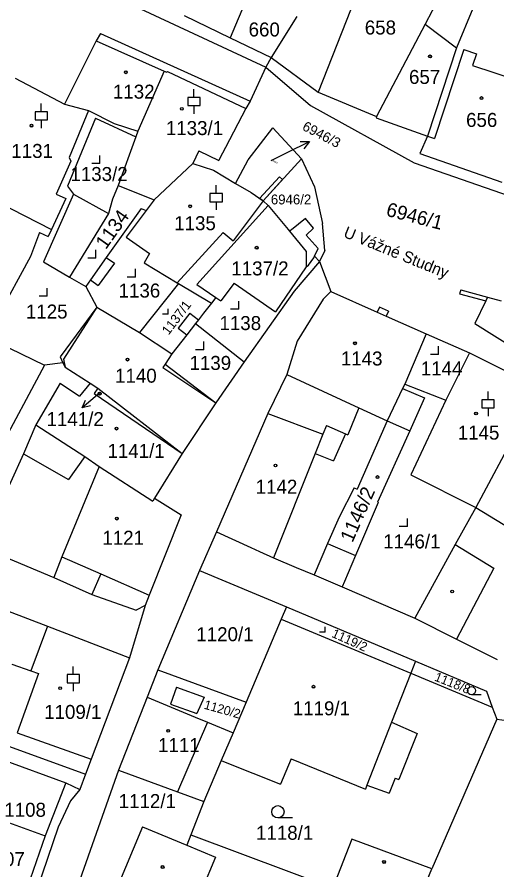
# Model space of a CAD drawing. Extents: x -593183 to -588034, y -1130415 to -1124994.
# Drawn here: x -591094.9 to -591036.6, y -1128971.4 to -1128867.8 of the extents above; entities that cross this region are included whole.
import ezdxf

# ---------------------------------------------------------------- set-up
doc = ezdxf.new("R2010")
doc.units = 0
for name, color, linetype in [('Vrstva 1', 7, 'Continuous'), ('Vrstva 15', 7, 'Continuous'), ('Vrstva 16', 7, 'Continuous'), ('Vrstva 18', 7, 'Continuous'), ('Vrstva 19', 7, 'Continuous'), ('Vrstva 25', 7, 'Continuous'), ('Vrstva 27', 7, 'Continuous'), ('Vrstva 4', 7, 'Continuous')]:
    doc.layers.add(name, color=color, linetype=linetype)

msp = doc.modelspace()

# ---------------------------------------------------------------- linework, layer by layer
at = {"layer": 'Vrstva 1'}
for p, q in [((-591051.99, -1128860.88), (-591058.32, -1128876.96)), ((-591042.27, -1128862.83), (-591045.35, -1128868.7)), ((-591066.71, -1128864.82), (-591069.01, -1128870.37)), ((-591074.6, -1128867.65), (-591069.01, -1128870.37)), ((-591060.94, -1128867.77), (-591064.03, -1128872.76)), ((-591039.55, -1128866.8), (-591041.52, -1128871.56)), ((-591045.35, -1128868.7), (-591051.24, -1128879.91)), ((-591085.29, -1128870.72), (-591089.14, -1128878.39)), ((-591085.29, -1128870.72), (-591077.03, -1128874.4)), ((-591069.01, -1128870.37), (-591064.03, -1128872.76)), ((-591041.52, -1128871.56), (-591045.06, -1128882.28)), ((-591064.03, -1128872.76), (-591064.7, -1128873.91)), ((-591064.03, -1128872.76), (-591058.32, -1128876.96)), ((-591064.7, -1128873.91), (-591066.58, -1128878.04)), ((-591077.03, -1128874.4), (-591080.25, -1128881.7)), ((-591077.03, -1128874.4), (-591076.7, -1128874.53)), ((-591076.64, -1128874.43), (-591076.7, -1128874.53)), ((-591076.64, -1128874.43), (-591067.1, -1128878.93)), ((-591095.14, -1128875.24), (-591089.14, -1128878.39)), ((-591058.32, -1128876.96), (-591051.24, -1128879.91)), ((-591066.58, -1128878.04), (-591067.1, -1128878.93)), ((-591089.14, -1128878.39), (-591086.22, -1128879.16)), ((-591086.22, -1128879.16), (-591088.58, -1128884.9)), ((-591086.22, -1128879.16), (-591083.09, -1128880.74)), ((-591067.1, -1128878.93), (-591069.59, -1128883.68)), ((-591085.38, -1128880.09), (-591088.79, -1128888.37)), ((-591085.38, -1128880.09), (-591080.47, -1128882.37)), ((-591051.24, -1128879.91), (-591051.28, -1128880.06)), ((-591051.28, -1128880.06), (-591045.06, -1128882.28)), ((-591083.09, -1128880.74), (-591080.25, -1128881.7)), ((-591080.25, -1128881.7), (-591080.47, -1128882.37)), ((-591066.83, -1128885.16), (-591063.83, -1128881.29)), ((-591063.83, -1128881.29), (-591060.37, -1128885.05)), ((-591045.06, -1128882.28), (-591045.98, -1128884.39)), ((-591080.47, -1128882.37), (-591082.61, -1128888.27)), ((-591072.81, -1128884.07), (-591073.57, -1128885.62)), ((-591072.81, -1128884.07), (-591070.41, -1128885.25)), ((-591069.59, -1128883.68), (-591070.3, -1128885.04)), ((-591045.98, -1128884.39), (-591036.02, -1128887.89)), ((-591088.36, -1128885.32), (-591090.17, -1128889.33)), ((-591088.58, -1128884.9), (-591088.36, -1128885.32)), ((-591070.3, -1128885.04), (-591070.41, -1128885.25)), ((-591068.37, -1128888.03), (-591066.83, -1128885.16)), ((-591065.02, -1128890.15), (-591060.37, -1128885.05)), ((-591060.37, -1128885.05), (-591058.79, -1128888.43)), ((-591073.57, -1128885.62), (-591078.24, -1128890.04)), ((-591073.57, -1128885.62), (-591071.04, -1128886.44)), ((-591071.04, -1128886.44), (-591068.37, -1128888.03)), ((-591101.51, -1128888.11), (-591090.72, -1128893.62)), ((-591088.79, -1128888.37), (-591088.04, -1128889.34)), ((-591082.61, -1128888.27), (-591083.32, -1128889.93)), ((-591082.61, -1128888.27), (-591078.24, -1128890.04)), ((-591068.37, -1128888.03), (-591066.47, -1128889.15)), ((-591058.79, -1128888.43), (-591057.81, -1128892.89)), ((-591088.04, -1128889.34), (-591091.69, -1128897.56)), ((-591090.17, -1128889.33), (-591088.99, -1128889.86)), ((-591066.47, -1128889.15), (-591065.02, -1128890.15)), ((-591088.99, -1128889.86), (-591090.72, -1128893.62)), ((-591083.32, -1128889.93), (-591083.78, -1128891.69)), ((-591078.24, -1128890.04), (-591079.23, -1128891.33)), ((-591065.02, -1128890.15), (-591068.66, -1128895)), ((-591065.02, -1128890.15), (-591064.39, -1128890.73)), ((-591079.83, -1128891.06), (-591084.06, -1128897.03)), ((-591079.23, -1128891.33), (-591081.65, -1128894.54)), ((-591079.83, -1128891.06), (-591079.23, -1128891.33)), ((-591064.39, -1128890.73), (-591073.07, -1128900.31)), ((-591064.39, -1128890.73), (-591061.98, -1128893.63)), ((-591083.78, -1128891.69), (-591088.52, -1128899.43)), ((-591059.87, -1128892.31), (-591061.58, -1128893.66)), ((-591058.9, -1128893.46), (-591059.87, -1128892.31)), ((-591090.72, -1128893.62), (-591091.11, -1128894.46)), ((-591061.98, -1128893.63), (-591061.81, -1128893.84)), ((-591061.58, -1128893.66), (-591061.81, -1128893.84)), ((-591059.77, -1128894.32), (-591058.9, -1128893.46)), ((-591057.51, -1128896.18), (-591057.81, -1128892.89)), ((-591092.18, -1128894.01), (-591093.28, -1128896.89)), ((-591092.18, -1128894.01), (-591091.11, -1128894.46)), ((-591081.65, -1128894.54), (-591078.8, -1128896.53)), ((-591069.86, -1128894.01), (-591075.45, -1128900.09)), ((-591069.86, -1128894.01), (-591068.66, -1128895)), ((-591058.33, -1128895.94), (-591059.77, -1128894.32)), ((-591078.8, -1128896.53), (-591079.48, -1128897.67)), ((-591058.76, -1128896.86), (-591058.33, -1128895.94)), ((-591057.51, -1128896.18), (-591058.18, -1128897.51)), ((-591093.28, -1128896.89), (-591098.41, -1128906.34)), ((-591091.69, -1128897.56), (-591088.52, -1128899.43)), ((-591084.06, -1128897.03), (-591085.98, -1128899.74)), ((-591079.48, -1128897.67), (-591075.45, -1128900.09)), ((-591058.18, -1128897.51), (-591061.26, -1128901.13)), ((-591059.52, -1128897.96), (-591058.86, -1128897.07)), ((-591058.86, -1128897.07), (-591058.76, -1128896.86)), ((-591058.18, -1128897.51), (-591058.76, -1128896.86)), ((-591058.18, -1128897.51), (-591056.81, -1128901.17)), ((-591059.77, -1128898.17), (-591063.53, -1128903.61)), ((-591059.77, -1128898.17), (-591059.52, -1128897.96)), ((-591088.52, -1128899.43), (-591086.56, -1128900.56)), ((-591085.98, -1128899.74), (-591086.56, -1128900.56)), ((-591086.56, -1128900.56), (-591085.23, -1128903.06)), ((-591075.28, -1128900.19), (-591080.02, -1128906.15)), ((-591075.45, -1128900.09), (-591075.28, -1128900.19)), ((-591073.07, -1128900.31), (-591070.75, -1128901.88)), ((-591068.52, -1128900.15), (-591070.14, -1128902.3)), ((-591068.52, -1128900.15), (-591063.53, -1128903.61)), ((-591070.75, -1128901.88), (-591071.3, -1128902.58)), ((-591070.75, -1128901.88), (-591070.14, -1128902.3)), ((-591061.26, -1128901.13), (-591067.34, -1128909.69)), ((-591056.81, -1128901.17), (-591057.74, -1128902.09)), ((-591056.81, -1128901.17), (-591051.17, -1128903.66)), ((-591037.77, -1128901.83), (-591037.98, -1128902.28)), ((-591037.77, -1128901.83), (-591036.1, -1128902.27)), ((-591071.3, -1128902.58), (-591072.25, -1128903.79)), ((-591057.74, -1128902.09), (-591060.9, -1128907.17)), ((-591037.98, -1128902.28), (-591039.3, -1128905.06)), ((-591085.23, -1128903.06), (-591089.65, -1128909.1)), ((-591085.23, -1128903.06), (-591080.02, -1128906.15)), ((-591072.25, -1128903.79), (-591072.88, -1128904.6)), ((-591051.17, -1128903.66), (-591050.07, -1128904.14)), ((-591073.24, -1128905.06), (-591074.29, -1128906.4)), ((-591072.88, -1128904.6), (-591073.24, -1128905.06)), ((-591073.24, -1128905.06), (-591067.34, -1128909.69)), ((-591050.07, -1128904.14), (-591045.2, -1128906.29)), ((-591039.3, -1128905.06), (-591031.08, -1128910.21)), ((-591098.31, -1128906.84), (-591091.56, -1128910.11)), ((-591080.02, -1128906.15), (-591076.1, -1128908.71)), ((-591074.29, -1128906.4), (-591076.1, -1128908.71)), ((-591060.9, -1128907.17), (-591062.14, -1128911.23)), ((-591045.2, -1128906.29), (-591047.79, -1128912.4)), ((-591045.2, -1128906.29), (-591039.97, -1128908.62)), ((-591089.65, -1128909.1), (-591089.36, -1128909.81)), ((-591076.1, -1128908.71), (-591076.93, -1128909.96)), ((-591039.97, -1128908.62), (-591042.81, -1128914.37)), ((-591039.97, -1128908.62), (-591031.44, -1128912.87)), ((-591091.56, -1128910.11), (-591098.56, -1128923.14)), ((-591089.36, -1128909.81), (-591091.56, -1128910.11)), ((-591089.36, -1128909.81), (-591089.06, -1128910.34)), ((-591076.93, -1128909.96), (-591070.76, -1128914.69)), ((-591067.34, -1128909.69), (-591070.76, -1128914.69)), ((-591089.06, -1128910.34), (-591086.04, -1128912.29)), ((-591062.14, -1128911.23), (-591064.46, -1128915.98)), ((-591089.66, -1128912.27), (-591092.62, -1128917.34)), ((-591089.66, -1128912.27), (-591087.31, -1128913.85)), ((-591086.04, -1128912.29), (-591087.31, -1128913.85)), ((-591086.04, -1128912.29), (-591085.1, -1128912.88)), ((-591085.1, -1128912.88), (-591085.53, -1128913.55)), ((-591085.1, -1128912.88), (-591074.83, -1128920.84)), ((-591048.08, -1128912.94), (-591049.94, -1128916.85)), ((-591047.79, -1128912.4), (-591048.08, -1128912.94)), ((-591047.79, -1128912.4), (-591042.81, -1128914.37)), ((-591031.44, -1128912.87), (-591039.19, -1128927.37)), ((-591085.53, -1128913.55), (-591074.83, -1128920.84)), ((-591042.81, -1128914.37), (-591047.09, -1128923.42)), ((-591070.76, -1128914.69), (-591074.83, -1128920.84)), ((-591064.46, -1128915.98), (-591070.68, -1128930.35)), ((-591064.46, -1128915.98), (-591057.76, -1128918.48)), ((-591092.62, -1128917.34), (-591094.1, -1128920.87)), ((-591049.94, -1128916.85), (-591053.58, -1128925.15)), ((-591049.94, -1128916.85), (-591047.21, -1128918.09)), ((-591057.76, -1128918.48), (-591058.7, -1128920.84)), ((-591047.21, -1128918.09), (-591051.12, -1128926.74)), ((-591094.1, -1128920.87), (-591099.1, -1128931.74)), ((-591094.1, -1128920.87), (-591088.66, -1128923.98)), ((-591086.68, -1128921.19), (-591088.66, -1128923.98)), ((-591086.68, -1128921.19), (-591084.94, -1128922.4)), ((-591074.83, -1128920.84), (-591078.2, -1128926.25)), ((-591058.7, -1128920.84), (-591063.76, -1128933.51)), ((-591084.94, -1128922.4), (-591078.43, -1128926.63)), ((-591047.09, -1128923.42), (-591039.19, -1128927.37)), ((-591053.97, -1128924.99), (-591055.8, -1128928.57)), ((-591053.97, -1128924.99), (-591053.58, -1128925.15)), ((-591078.2, -1128926.25), (-591078.43, -1128926.63)), ((-591078.2, -1128926.25), (-591074.99, -1128928.29)), ((-591051.03, -1128926.78), (-591053.79, -1128933.21)), ((-591051.12, -1128926.74), (-591051.03, -1128926.78)), ((-591039.19, -1128927.37), (-591041.71, -1128931.87)), ((-591074.99, -1128928.29), (-591078.85, -1128938.01)), ((-591055.8, -1128928.57), (-591057.18, -1128931.76)), ((-591070.68, -1128930.35), (-591072.75, -1128935.02)), ((-591070.68, -1128930.35), (-591066.5, -1128932.26)), ((-591057.18, -1128931.76), (-591058.81, -1128935.54)), ((-591057.18, -1128931.76), (-591056.82, -1128931.91)), ((-591056.82, -1128931.91), (-591053.79, -1128933.21)), ((-591041.71, -1128931.87), (-591046.61, -1128940.82)), ((-591098.01, -1128932.7), (-591090.43, -1128935.9)), ((-591066.5, -1128932.26), (-591065.47, -1128932.73)), ((-591065.47, -1128932.73), (-591063.76, -1128933.51)), ((-591063.76, -1128933.51), (-591061.02, -1128934.66)), ((-591072.75, -1128935.02), (-591077.82, -1128947.1)), ((-591072.75, -1128935.02), (-591062.19, -1128939.46)), ((-591061.02, -1128934.66), (-591058.81, -1128935.54)), ((-591090.43, -1128935.9), (-591085.84, -1128937.95)), ((-591058.81, -1128935.54), (-591055.42, -1128937.01)), ((-591055.42, -1128937.01), (-591046.61, -1128940.82)), ((-591085.84, -1128937.95), (-591080.43, -1128939.84)), ((-591078.85, -1128938.01), (-591079.35, -1128939.28)), ((-591079.35, -1128939.28), (-591081.24, -1128945.62)), ((-591079.35, -1128939.28), (-591080.43, -1128939.84)), ((-591096.05, -1128939.94), (-591091.21, -1128941.8)), ((-591062.19, -1128939.46), (-591062.82, -1128940.94)), ((-591062.19, -1128939.46), (-591046.51, -1128946.03)), ((-591062.82, -1128940.94), (-591067.09, -1128951.04)), ((-591062.82, -1128940.94), (-591047.08, -1128947.49)), ((-591046.61, -1128940.82), (-591041.54, -1128943.37)), ((-591091.21, -1128941.8), (-591081.24, -1128945.62)), ((-591041.54, -1128943.37), (-591036.59, -1128945.84)), ((-591081.24, -1128945.62), (-591085.9, -1128957.94)), ((-591046.51, -1128946.03), (-591047.08, -1128947.49)), ((-591046.51, -1128946.03), (-591037.89, -1128949.67)), ((-591077.82, -1128947.1), (-591079.12, -1128950.43)), ((-591077.82, -1128947.1), (-591067.09, -1128951.04)), ((-591047.08, -1128947.49), (-591049.41, -1128953.45)), ((-591047.08, -1128947.49), (-591037.19, -1128951.61)), ((-591079.12, -1128950.43), (-591082.57, -1128959.29)), ((-591079.12, -1128950.43), (-591076.69, -1128951.44)), ((-591037.89, -1128949.67), (-591037.19, -1128951.61)), ((-591076.69, -1128951.44), (-591073.29, -1128952.84)), ((-591067.09, -1128951.04), (-591068.66, -1128954.76)), ((-591037.19, -1128951.61), (-591036.65, -1128953.09)), ((-591073.29, -1128952.84), (-591071.79, -1128953.46)), ((-591071.79, -1128953.46), (-591068.66, -1128954.76)), ((-591049.41, -1128953.45), (-591046.31, -1128954.81)), ((-591036.65, -1128953.09), (-591044.51, -1128971.27)), ((-591036.65, -1128953.09), (-591021.77, -1128955.01)), ((-591068.66, -1128954.76), (-591070.1, -1128958.12)), ((-591046.31, -1128954.81), (-591048.53, -1128960.43)), ((-591096.71, -1128956.08), (-591086.59, -1128959.76)), ((-591061.6, -1128957.91), (-591062.91, -1128960.96)), ((-591061.6, -1128957.91), (-591052.59, -1128961.59)), ((-591096.73, -1128958), (-591088.99, -1128960.83)), ((-591085.9, -1128957.94), (-591086.59, -1128959.76)), ((-591070.1, -1128958.12), (-591072.2, -1128963.09)), ((-591070.1, -1128958.12), (-591069.63, -1128958.31)), ((-591069.63, -1128958.31), (-591062.91, -1128960.96)), ((-591082.57, -1128959.29), (-591087.52, -1128973.28)), ((-591086.59, -1128959.76), (-591087.29, -1128961.61)), ((-591082.57, -1128959.29), (-591075.43, -1128961.91)), ((-591088.99, -1128960.83), (-591091.5, -1128967.24)), ((-591088.99, -1128960.83), (-591087.29, -1128961.61)), ((-591048.99, -1128960.25), (-591049.71, -1128962.06)), ((-591048.99, -1128960.25), (-591048.53, -1128960.43)), ((-591075.43, -1128961.91), (-591072.2, -1128963.09)), ((-591052.41, -1128961.12), (-591052.59, -1128961.59)), ((-591052.41, -1128961.12), (-591049.71, -1128962.06)), ((-591072.2, -1128963.09), (-591073.78, -1128967.13)), ((-591099.09, -1128964.52), (-591091.5, -1128967.24)), ((-591079.68, -1128966.15), (-591083.27, -1128974.76)), ((-591079.68, -1128966.15), (-591074.29, -1128968.39)), ((-591091.5, -1128967.24), (-591093.68, -1128973.55)), ((-591073.78, -1128967.13), (-591074.29, -1128968.39)), ((-591073.78, -1128967.13), (-591047.03, -1128977.11)), ((-591054.24, -1128967.67), (-591056.33, -1128973.04)), ((-591044.51, -1128971.27), (-591054.24, -1128967.67)), ((-591074.29, -1128968.39), (-591070.81, -1128969.83)), ((-591070.81, -1128969.83), (-591074.46, -1128978.6)), ((-591046.85, -1128976.69), (-591044.51, -1128971.27))]:
    msp.add_line(p, q, dxfattribs=at)
at = {"layer": 'Vrstva 16'}
msp.add_line((-591064.06, -1128885.25), (-591062.08, -1128884.28), dxfattribs=at)
at = {"layer": 'Vrstva 25'}
for p, q in [((-591073.43, -1128877.58), (-591073.43, -1128876.58)), ((-591091.97, -1128879.32), (-591091.97, -1128878.32)), ((-591073.43, -1128878.58), (-591073.43, -1128879.58)), ((-591091.97, -1128880.32), (-591091.97, -1128881.32)), ((-591062.08, -1128884.28), (-591059.38, -1128882.96)), ((-591084.83, -1128885.63), (-591084.83, -1128884.63)), ((-591084.83, -1128885.63), (-591085.83, -1128885.63)), ((-591070.72, -1128889.25), (-591070.72, -1128888.25)), ((-591070.72, -1128890.25), (-591070.72, -1128891.25)), ((-591085.32, -1128897.09), (-591085.32, -1128896.09)), ((-591085.32, -1128897.09), (-591086.32, -1128897.09)), ((-591080.52, -1128899.4), (-591080.52, -1128898.4)), ((-591080.52, -1128899.4), (-591081.52, -1128899.4)), ((-591091.23, -1128901.74), (-591091.23, -1128900.74)), ((-591091.23, -1128901.74), (-591092.23, -1128901.74)), ((-591067.97, -1128903.31), (-591067.97, -1128902.31)), ((-591076.55, -1128903.91), (-591077.22, -1128903.91)), ((-591076.55, -1128903.91), (-591076.55, -1128903.24)), ((-591067.97, -1128903.31), (-591068.97, -1128903.31)), ((-591072.23, -1128908.23), (-591072.23, -1128907.23)), ((-591043.7, -1128908.81), (-591043.7, -1128907.81)), ((-591072.23, -1128908.23), (-591073.23, -1128908.23)), ((-591043.7, -1128908.81), (-591044.7, -1128908.81)), ((-591037.69, -1128914.29), (-591037.69, -1128913.29)), ((-591084.9, -1128913.49), (-591086.98, -1128915.3)), ((-591037.69, -1128915.29), (-591037.69, -1128916.29)), ((-591047.49, -1128929.7), (-591047.49, -1128928.7)), ((-591047.49, -1128929.7), (-591048.49, -1128929.7)), ((-591057.49, -1128942.53), (-591057.49, -1128941.86)), ((-591057.49, -1128942.53), (-591058.16, -1128942.53)), ((-591088.07, -1128947.68), (-591088.07, -1128946.68)), ((-591088.07, -1128948.68), (-591088.07, -1128949.68)), ((-591038.54, -1128950.12), (-591039.71, -1128950.12)), ((-591061.47, -1128965.08), (-591063.22, -1128965.08))]:
    msp.add_line(p, q, dxfattribs=at)
for points in [[(-591074.18, -1128878.58), (-591072.68, -1128878.58), (-591072.68, -1128877.58), (-591074.18, -1128877.58)], [(-591092.72, -1128880.32), (-591091.22, -1128880.32), (-591091.22, -1128879.32), (-591092.72, -1128879.32)], [(-591071.47, -1128890.25), (-591069.97, -1128890.25), (-591069.97, -1128889.25), (-591071.47, -1128889.25)], [(-591038.44, -1128915.29), (-591036.94, -1128915.29), (-591036.94, -1128914.29), (-591038.44, -1128914.29)], [(-591088.82, -1128948.68), (-591087.32, -1128948.68), (-591087.32, -1128947.68), (-591088.82, -1128947.68)]]:
    msp.add_lwpolyline(points, close=True, dxfattribs=at)
for points in [[(-591060.5, -1128882.95), (-591059.38, -1128882.96), (-591060.06, -1128883.85)], [(-591085.99, -1128915.04), (-591086.98, -1128915.3), (-591086.59, -1128914.35)]]:
    msp.add_lwpolyline(points, dxfattribs=at)
for centre, radius in [((-591044.75, -1128872.61), 0.175), ((-591044.75, -1128872.61), 0.15), ((-591081.69, -1128874.53), 0.175), ((-591081.69, -1128874.53), 0.15), ((-591038.5, -1128877.67), 0.175), ((-591038.5, -1128877.67), 0.15), ((-591074.89, -1128878.97), 0.175), ((-591074.89, -1128878.97), 0.15), ((-591093.15, -1128881.02), 0.175), ((-591093.15, -1128881.02), 0.15), ((-591073.88, -1128890.81), 0.175), ((-591073.88, -1128890.81), 0.15), ((-591065.8, -1128895.84), 0.175), ((-591065.8, -1128895.84), 0.15), ((-591053.87, -1128907.44), 0.175), ((-591053.87, -1128907.44), 0.15), ((-591081.49, -1128909.42), 0.175), ((-591081.49, -1128909.42), 0.15), ((-591084.87, -1128913.56), 0.175), ((-591084.87, -1128913.56), 0.15), ((-591039.16, -1128915.97), 0.175), ((-591039.16, -1128915.97), 0.15), ((-591082.82, -1128917.8), 0.175), ((-591082.82, -1128917.8), 0.15), ((-591063.52, -1128922.28), 0.175), ((-591063.52, -1128922.28), 0.15), ((-591051.13, -1128923.69), 0.175), ((-591051.13, -1128923.69), 0.15), ((-591082.79, -1128928.73), 0.175), ((-591082.79, -1128928.73), 0.15), ((-591042.06, -1128937.58), 0.175), ((-591089.67, -1128949.32), 0.175), ((-591089.67, -1128949.32), 0.15), ((-591058.9, -1128949.15), 0.175), ((-591058.9, -1128949.15), 0.15), ((-591039.71, -1128949.62), 0.503), ((-591076.55, -1128954.51), 0.175), ((-591076.55, -1128954.51), 0.15), ((-591063.22, -1128964.33), 0.75), ((-591050.33, -1128970.43), 0.175), ((-591050.33, -1128970.43), 0.15), ((-591077.23, -1128971.04), 0.175), ((-591077.23, -1128971.04), 0.15)]:
    msp.add_circle(centre, radius, dxfattribs=at)
at = {"layer": 'Vrstva 27'}
for p, q in [((-591065.44, -1128889.86), (-591063.03, -1128887.22)), ((-591063.03, -1128887.22), (-591062.66, -1128887.56)), ((-591062.66, -1128887.56), (-591065.02, -1128890.15)), ((-591065.02, -1128890.15), (-591065.44, -1128889.86))]:
    msp.add_line(p, q, dxfattribs=at)
at = {"layer": 'Vrstva 4'}
for p, q in [((-591084.06, -1128864.87), (-591064.7, -1128873.91)), ((-591045.35, -1128868.7), (-591041.52, -1128871.56)), ((-591084.75, -1128869.81), (-591085.29, -1128870.72)), ((-591084.75, -1128869.81), (-591066.58, -1128878.04)), ((-591040.63, -1128871.78), (-591044.21, -1128882.59)), ((-591040.63, -1128871.78), (-591039.1, -1128872.28)), ((-591039.1, -1128872.28), (-591039.57, -1128873.71)), ((-591064.7, -1128873.91), (-591059.28, -1128878.58)), ((-591039.57, -1128873.71), (-591034.39, -1128875.42)), ((-591059.28, -1128878.58), (-591046.66, -1128885.54)), ((-591045.06, -1128882.28), (-591044.21, -1128882.59)), ((-591046.66, -1128885.54), (-591027, -1128892.39)), ((-591088.04, -1128889.34), (-591083.78, -1128891.69)), ((-591061.81, -1128893.84), (-591059.78, -1128896.28)), ((-591059.78, -1128896.28), (-591059.77, -1128898.17)), ((-591083.06, -1128897.73), (-591085.04, -1128900.41)), ((-591084.06, -1128897.03), (-591083.06, -1128897.73)), ((-591085.98, -1128899.74), (-591085.04, -1128900.41)), ((-591075.28, -1128900.19), (-591071.3, -1128902.58)), ((-591041.02, -1128900.97), (-591041.15, -1128901.45)), ((-591041.15, -1128901.45), (-591037.98, -1128902.28)), ((-591041.02, -1128900.97), (-591037.77, -1128901.83)), ((-591085.23, -1128903.06), (-591089.27, -1128909.38)), ((-591073.9, -1128903.79), (-591075.32, -1128905.6)), ((-591073.9, -1128903.79), (-591072.88, -1128904.6)), ((-591050.9, -1128903.04), (-591051.17, -1128903.66)), ((-591049.8, -1128903.53), (-591050.9, -1128903.04)), ((-591049.8, -1128903.53), (-591050.07, -1128904.14)), ((-591075.32, -1128905.6), (-591074.29, -1128906.4)), ((-591089.27, -1128909.38), (-591089.06, -1128910.34)), ((-591076.93, -1128909.96), (-591077.21, -1128910.39)), ((-591077.21, -1128910.39), (-591070.76, -1128914.69)), ((-591062.14, -1128911.23), (-591053.38, -1128915.28)), ((-591048.08, -1128912.94), (-591045.4, -1128914.08)), ((-591045.4, -1128914.08), (-591047.21, -1128918.09)), ((-591053.38, -1128915.28), (-591054.71, -1128918.55)), ((-591053.38, -1128915.28), (-591049.94, -1128916.85)), ((-591092.62, -1128917.34), (-591086.68, -1128921.19)), ((-591057.34, -1128917.42), (-591057.76, -1128918.48)), ((-591057.34, -1128917.42), (-591055.01, -1128918.42)), ((-591055.01, -1128918.42), (-591056.49, -1128921.73)), ((-591055.01, -1128918.42), (-591054.71, -1128918.55)), ((-591058.7, -1128920.84), (-591056.49, -1128921.73)), ((-591084.94, -1128922.4), (-591089.47, -1128933.39)), ((-591039.19, -1128927.37), (-591032.18, -1128931.66)), ((-591041.71, -1128931.87), (-591036.99, -1128934.77)), ((-591089.47, -1128933.39), (-591090.43, -1128935.9)), ((-591089.47, -1128933.39), (-591084.73, -1128935.45)), ((-591053.79, -1128933.21), (-591055.14, -1128936.35)), ((-591036.99, -1128934.77), (-591041.54, -1128943.37)), ((-591084.73, -1128935.45), (-591085.84, -1128937.95)), ((-591084.73, -1128935.45), (-591078.85, -1128938.01)), ((-591055.14, -1128936.35), (-591055.42, -1128937.01)), ((-591091.21, -1128941.8), (-591093.21, -1128947.23)), ((-591095.53, -1128946.41), (-591093.21, -1128947.23)), ((-591092.31, -1128947.55), (-591094.87, -1128954.76)), ((-591093.21, -1128947.23), (-591092.31, -1128947.55)), ((-591075.54, -1128949.22), (-591076.27, -1128951.25)), ((-591075.54, -1128949.22), (-591072.17, -1128950.43)), ((-591072.17, -1128950.43), (-591073.08, -1128952.38)), ((-591076.27, -1128951.25), (-591073.08, -1128952.38)), ((-591071.79, -1128953.46), (-591075.43, -1128961.91)), ((-591049.41, -1128953.45), (-591052.41, -1128961.12)), ((-591094.87, -1128954.76), (-591085.9, -1128957.94)), ((-591087.29, -1128961.61), (-591088.41, -1128963.01)), ((-591088.41, -1128963.01), (-591089.91, -1128966.19)), ((-591089.91, -1128966.19), (-591117, -1129045.34))]:
    msp.add_line(p, q, dxfattribs=at)

# ---------------------------------------------------------------- texts
at = {"layer": 'Vrstva 15'}
msp.add_text('U Vážné Studny', height=1.4, rotation=337.8716, dxfattribs=at).set_placement((-591055.36, -1128894.5))
at = {"layer": 'Vrstva 16'}
msp.add_text('6946/3', height=1.2, rotation=332.3048, dxfattribs=at).set_placement((-591060.36, -1128881.48))
msp.add_text('1141/2', height=1.7, dxfattribs=at).set_placement((-591091.32, -1128917.5))
at = {"layer": 'Vrstva 18'}
for s, height, rotation, p in [('6946/3', 0.2, 332.3048, (-591064.06, -1128885.25)), ('6946/1', 1.7, 345.4952, (-591050.18, -1128891.94)), ('1118/8', 1.1, 338.0912, (-591044.3, -1128948.37)), ('1120/2', 1.1, 344.2532, (-591072.28, -1128951.8))]:
    msp.add_text(s, height=height, rotation=rotation, dxfattribs=at).set_placement(p)
for s, height, p in [('6946/2', 1.2, (-591064.08, -1128890.58)), ('1120/1', 1.7, (-591073.13, -1128943.62)), ('1112/1', 1.7, (-591082.56, -1128963.88)), ('1118/1', 1.7, (-591065.88, -1128967.73))]:
    msp.add_text(s, height=height, dxfattribs=at).set_placement(p)
at = {"layer": 'Vrstva 19'}
for s, height, p in [('660', 1.7, (-591066.78, -1128870.19)), ('658', 1.7, (-591052.67, -1128869.95)), ('657', 1.7, (-591047.3, -1128875.95)), ('1132', 1.7, (-591083.26, -1128877.74)), ('656', 1.7, (-591040.37, -1128881.17)), ('1133/1', 1.7, (-591076.83, -1128882.16)), ('1131', 1.7, (-591095.6, -1128884.94)), ('1133/2', 1.7, (-591088.42, -1128887.74)), ('1135', 1.7, (-591075.82, -1128893.71)), ('1137/2', 1.7, (-591068.88, -1128899.2)), ('1136', 1.7, (-591082.57, -1128901.89)), ('1125', 1.7, (-591093.83, -1128904.44)), ('1138', 1.7, (-591070.32, -1128905.84)), ('1139', 1.7, (-591073.96, -1128910.68)), ('1143', 1.7, (-591055.58, -1128910.14)), ('1144', 1.7, (-591045.87, -1128911.35)), ('1140', 1.7, (-591083, -1128912.23)), ('1141/2', 0.01, (-591084.9, -1128913.49)), ('1145', 1.7, (-591041.38, -1128919.14)), ('1141/1', 1.7, (-591083.92, -1128921.36)), ('1142', 1.7, (-591065.92, -1128925.71)), ('1121', 1.7, (-591084.54, -1128931.91)), ('1146/1', 1.7, (-591050.43, -1128932.35)), ('1109/1', 1.7, (-591091.61, -1128953.06)), ('1119/1', 1.7, (-591061.42, -1128952.62)), ('1111', 1.7, (-591077.78, -1128957.08)), ('1108', 1.7, (-591096.45, -1128964.94)), ('1107', 1.7, (-591099.02, -1128970.93))]:
    msp.add_text(s, height=height, dxfattribs=at).set_placement(p)
for s, height, rotation, p in [('1134', 1.7, 54.6808, (-591084.12, -1128896.14)), ('1137/1', 1.14, 52.7477, (-591076.5, -1128906.51)), ('1146/2', 1.7, 66.2677, (-591054.17, -1128931.73)), ('1119/2', 1.1, 335.8745, (-591056.78, -1128943.07))]:
    msp.add_text(s, height=height, rotation=rotation, dxfattribs=at).set_placement(p)

doc.saveas('drawing.dxf')
